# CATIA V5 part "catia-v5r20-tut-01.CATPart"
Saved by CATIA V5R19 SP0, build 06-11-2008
Part number: c04tut01
Material "Copper": density 8900 kg/m3, Young's modulus 1.1e+11 Pa, Poisson ratio 0.33, thermal expansion 1.65e-05 1/K
Bounding box of the stored display mesh (mm): x -99.637 to 99.637, y -99.817 to 99.817, z 0 to 140
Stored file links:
  D:\Shriniwas\v5_r19\Part files\c04\c04tut01.CATPart
  C:\Program Files (x86)\Dassault Systemes\B19\intel_a\startup\materials\Catalog.CATMaterial
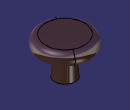
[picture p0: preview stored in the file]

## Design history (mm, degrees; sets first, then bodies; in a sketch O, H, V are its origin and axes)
Body1 (main body), material "Copper"
  Sketch1 on yz-plane, origin (0, 0, 0), H (0, 1, 0), V (0, 0, 1)
    axis line L1 (0, 92.904) -> (0, -81.406)
    point P1 (0, 92.904)
    line L2 (0, 0) -> (40, 0)
    line L3 (40, 0) -> (40, 70)
    line L4 (60, 90) -> (75, 90)
    arc A1 centre (75, 115) radius 25 from (75, 90) to (75, 140) ccw
    line L5 (75, 140) -> (0, 140)
    point P7 (0, 140)
    line L6 (0, 140) -> (0, 0)
    arc A2 centre (60, 70) radius 20 from (40, 70) to (60, 90) cw
    radius A2 = 20
    "Radius" L3 L1 = 40
    "Radius" L1 A1 = 100
    radius A1 = 25
    distance L2 L5 = 140
    coincidence: P1 V, P7 V
    vertical: L1 V, L3 V, L6 V
    horizontal: L2 H, L4 H
    tangency: A1 L4, L5 A1, A2 L3, A2 L4
  Shaft1: profile Sketch1, axis Sketch1.L1, angle 360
